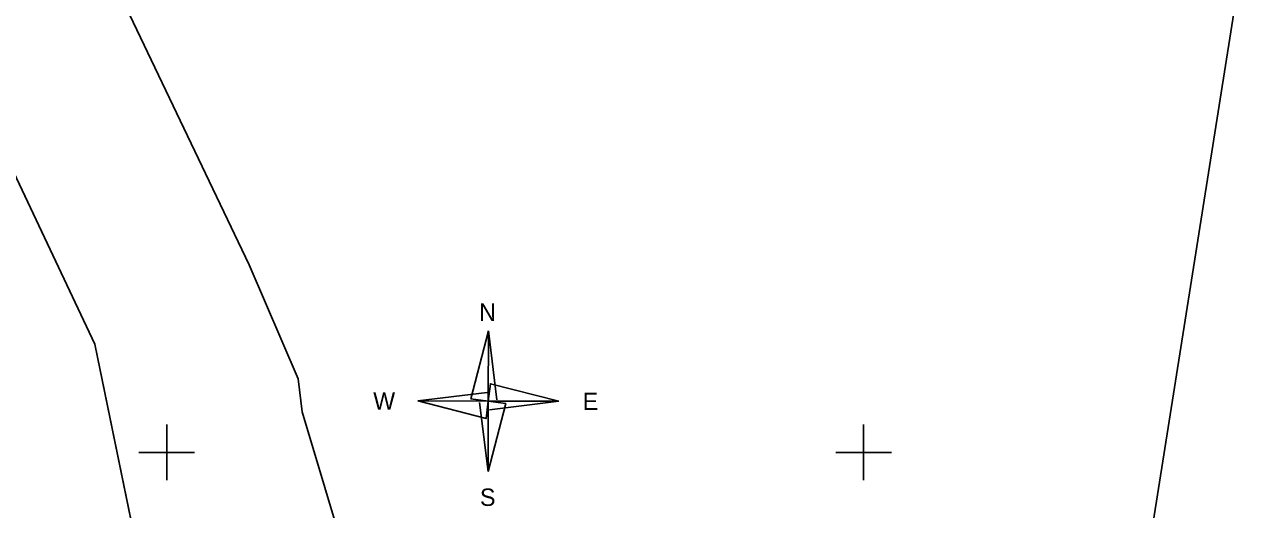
# Model space of a CAD drawing. Extents: x 543497 to 552146, y 6567125 to 6579845.
# Drawn here: x 545889.8 to 545977.3, y 6577695.9 to 6577730.7 of the extents above; entities that cross this region are included whole.
import ezdxf

# ---------------------------------------------------------------- set-up
doc = ezdxf.new("R2010")
doc.units = 0
for name, color, linetype in [('xref_Kangru tee 1_geodeesia$0$PIIR', 7, 'Continuous'), ('xref_Kangru tee 1_geodeesia$0$vork', 7, 'Continuous'), ('xref_Kangru tee 1_geodeesia$0$VORMISTUS', 7, 'Continuous')]:
    doc.layers.add(name, color=color, linetype=linetype)

# ---------------------------------------------------------------- blocks, each defined once
blk = doc.blocks.new('xref_Kangru tee 1_geodeesia$0$reinord')
for p, q in [((0.012, 5.052), (0.619, 0.089)), ((-5.052, 0.012), (-0.089, 0.619)), ((-0.012, -5.052), (-0.619, -0.089)), ((5.052, -0.012), (0.089, -0.619))]:
    blk.add_line(p, q)
for points in [[(0.012, 5.052), (-1.25, 0.159), (0, 0)], [(5.052, -0.012), (0.159, 1.25), (0, 0)], [(-5.052, 0.012), (-0.159, -1.25), (0, 0)], [(-0.012, -5.052), (1.25, -0.159), (0, 0)]]:
    blk.add_lwpolyline(points, close=True)
for s, p in [('N', (-0.657, 5.761)), ('W', (-8.259, -0.608)), ('E', (6.776, -0.642)), ('S', (-0.598, -7.52))]:
    blk.add_text(s, height=1.25).set_placement(p)
blk = doc.blocks.new('xref_Kangru tee 1_geodeesia$0$VKORIS')
for p, q in [((0, 4), (0, -4)), ((-4, 0), (4, 0))]:
    blk.add_line(p, q)

msp = doc.modelspace()

# ---------------------------------------------------------------- linework, layer by layer
at = {"layer": 'xref_Kangru tee 1_geodeesia$0$PIIR'}
for points in [[(545872.69, 6577782.96), (545871.05, 6577786.39), (545874.7, 6577788.05), (545922.19, 6577809.68), (545973.61, 6577832.94), (545956.36, 6577869.23), (545939.5, 6577905.43), (546028.71, 6577946.4), (546081.11, 6577806.12), (545983.53, 6577775.51), (545969.55, 6577687.28), (545921.7, 6577673.29), (545918.84, 6577672.45), (545911.34, 6577697.47), (545909.71, 6577702.91), (545909.43, 6577705.29), (545905.92, 6577713.46), (545874.41, 6577779.36), (545872.69, 6577782.96)], [(545925.88, 6577650.4), (545907.89, 6577644.25), (545894.83, 6577707.76), (545862.97, 6577775.32), (545825.49, 6577853.01)], [(545858.78, 6577811.93), (545870.6, 6577787.32), (545871.05, 6577786.39), (545872.69, 6577782.96), (545874.41, 6577779.36), (545905.92, 6577713.46), (545909.43, 6577705.29), (545909.71, 6577702.91), (545911.34, 6577697.47), (545918.84, 6577672.45), (545925.88, 6577650.4)], [(545983.53, 6577775.51), (546081.11, 6577806.12), (546096.86, 6577764.18), (546079.41, 6577756.98), (546054.12, 6577754.83), (546055.48, 6577740.79), (546080.65, 6577742.83), (546099.69, 6577747.34), (546110.26, 6577728.46), (545969.55, 6577687.28), (545983.53, 6577775.51)], [(545870.16, 6577632.94), (545821.56, 6577614.29), (545789.82, 6577704.15), (545884.18, 6577730.34), (545894.83, 6577707.76), (545907.38, 6577646.71), (545870.16, 6577632.94)]]:
    msp.add_lwpolyline(points, dxfattribs=at)

# ---------------------------------------------------------------- block references
at = {"layer": 'xref_Kangru tee 1_geodeesia$0$vork', "xscale": 0.5, "yscale": 0.5}
for p in [(545900, 6577700), (545950, 6577700)]:
    msp.add_blockref('xref_Kangru tee 1_geodeesia$0$VKORIS', p, dxfattribs=at)
at = {"layer": 'xref_Kangru tee 1_geodeesia$0$VORMISTUS'}
msp.add_blockref('xref_Kangru tee 1_geodeesia$0$reinord', (545923.073, 6577703.678), dxfattribs=at)

doc.saveas('drawing.dxf')
